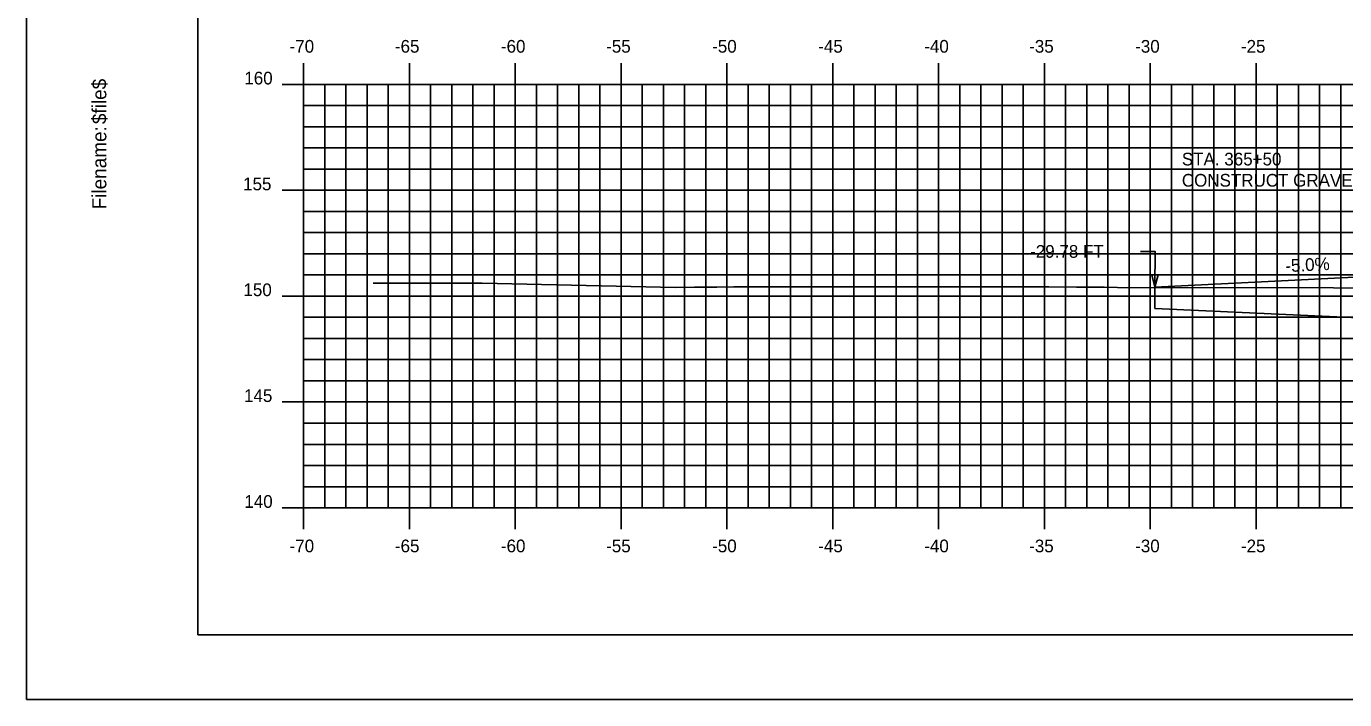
# Model space of a CAD drawing. Extents: x 1147412 to 1147582, y 608981 to 609091.
# Drawn here: x 1147411.6 to 1147473.9, y 608981.3 to 609013.1 of the extents above; entities that cross this region are included whole.
import ezdxf

# ---------------------------------------------------------------- set-up
doc = ezdxf.new("R2010")
doc.units = 0
for name, color, linetype in [('ANNOTATION', 7, 'Continuous'), ('BORDER', 7, 'Continuous'), ('D_Roadway_SubGrade', 7, 'Continuous'), ('D_Text_Standard', 7, 'Continuous'), ('H_V ANNOTATION', 7, 'Continuous'), ('MAJOR', 7, 'Continuous'), ('MINOR', 7, 'Continuous'), ('PLOT BOUNDARY', 7, 'Continuous'), ('S_Roadway_Centerline', 7, 'Continuous')]:
    doc.layers.add(name, color=color, linetype=linetype)

msp = doc.modelspace()

# ---------------------------------------------------------------- linework, layer by layer
msp.add_lwpolyline([(1147464.922, 609000.756), (1147479.697, 609001.495), (1147483.697, 609001.655), (1147494.697, 609001.875), (1147505.697, 609001.655), (1147509.697, 609001.495), (1147517.421, 608998.921), (1147520.421, 608997.921), (1147520.898, 608998.159), (1147522.148, 608998.709), (1147523.398, 608999.109), (1147524.648, 608999.359), (1147525.898, 608999.459)])
at = {"layer": 'BORDER'}
msp.add_lwpolyline([(1147419.698, 608984.335), (1147579.698, 608984.335), (1147579.698, 609089.335), (1147419.698, 609089.335)], close=True, dxfattribs=at)
at = {"layer": 'D_Roadway_SubGrade'}
msp.add_lwpolyline([(1147464.922, 608999.756), (1147479.697, 608999.075), (1147483.697, 608999.155), (1147483.697, 609001.239), (1147483.697, 609001.405), (1147479.697, 609001.245), (1147479.697, 609001.495), (1147464.922, 609000.756)], close=True, dxfattribs=at)
at = {"layer": 'D_Text_Standard'}
msp.add_lwpolyline([(1147464.922, 609000.756), (1147464.924, 609002.448), (1147464.244, 609002.448)], dxfattribs=at)
msp.add_lwpolyline([(1147464.922, 609000.756), (1147464.777, 609001.339), (1147465.068, 609001.338)], close=True, dxfattribs=at)
at = {"layer": 'MAJOR'}
for p, q in [((1147424.697, 609011.337), (1147424.697, 609010.335)), ((1147429.697, 609011.337), (1147429.697, 609010.335)), ((1147434.697, 609011.337), (1147434.697, 609010.335)), ((1147439.697, 609011.337), (1147439.697, 609010.335)), ((1147444.697, 609011.337), (1147444.697, 609010.335)), ((1147449.697, 609011.337), (1147449.697, 609010.335)), ((1147454.697, 609011.337), (1147454.697, 609010.335)), ((1147459.697, 609011.337), (1147459.697, 609010.335)), ((1147464.697, 609011.337), (1147464.697, 609010.335)), ((1147469.697, 609011.337), (1147469.697, 609010.335)), ((1147423.695, 609010.335), (1147424.697, 609010.335)), ((1147424.697, 609010.335), (1147564.697, 609010.335)), ((1147424.697, 608990.335), (1147424.697, 609010.335)), ((1147424.697, 608990.335), (1147424.697, 609010.335)), ((1147424.697, 609010.335), (1147564.697, 609010.335)), ((1147429.697, 608990.335), (1147429.697, 609010.335)), ((1147434.697, 608990.335), (1147434.697, 609010.335)), ((1147439.697, 608990.335), (1147439.697, 609010.335)), ((1147444.697, 608990.335), (1147444.697, 609010.335)), ((1147449.697, 608990.335), (1147449.697, 609010.335)), ((1147454.697, 608990.335), (1147454.697, 609010.335)), ((1147459.697, 608990.335), (1147459.697, 609010.335)), ((1147464.697, 608990.335), (1147464.697, 609010.335)), ((1147469.697, 608990.335), (1147469.697, 609010.335)), ((1147423.695, 609005.335), (1147424.697, 609005.335)), ((1147424.697, 609005.335), (1147564.697, 609005.335)), ((1147423.695, 609000.335), (1147424.697, 609000.335)), ((1147424.697, 609000.335), (1147564.697, 609000.335)), ((1147423.695, 608995.335), (1147424.697, 608995.335)), ((1147424.697, 608995.335), (1147564.697, 608995.335)), ((1147423.695, 608990.335), (1147424.697, 608990.335)), ((1147424.697, 608990.335), (1147564.697, 608990.335)), ((1147424.697, 608990.335), (1147564.697, 608990.335)), ((1147424.697, 608989.333), (1147424.697, 608990.335)), ((1147429.697, 608989.333), (1147429.697, 608990.335)), ((1147434.697, 608989.333), (1147434.697, 608990.335)), ((1147439.697, 608989.333), (1147439.697, 608990.335)), ((1147444.697, 608989.333), (1147444.697, 608990.335)), ((1147449.697, 608989.333), (1147449.697, 608990.335)), ((1147454.697, 608989.333), (1147454.697, 608990.335)), ((1147459.697, 608989.333), (1147459.697, 608990.335)), ((1147464.697, 608989.333), (1147464.697, 608990.335)), ((1147469.697, 608989.333), (1147469.697, 608990.335))]:
    msp.add_line(p, q, dxfattribs=at)
at = {"layer": 'MINOR'}
for p, q in [((1147425.697, 608990.335), (1147425.697, 609010.335)), ((1147426.697, 608990.335), (1147426.697, 609010.335)), ((1147427.697, 608990.335), (1147427.697, 609010.335)), ((1147428.697, 608990.335), (1147428.697, 609010.335)), ((1147430.697, 608990.335), (1147430.697, 609010.335)), ((1147431.697, 608990.335), (1147431.697, 609010.335)), ((1147432.697, 608990.335), (1147432.697, 609010.335)), ((1147433.697, 608990.335), (1147433.697, 609010.335)), ((1147435.697, 608990.335), (1147435.697, 609010.335)), ((1147436.697, 608990.335), (1147436.697, 609010.335)), ((1147437.697, 608990.335), (1147437.697, 609010.335)), ((1147438.697, 608990.335), (1147438.697, 609010.335)), ((1147440.697, 608990.335), (1147440.697, 609010.335)), ((1147441.697, 608990.335), (1147441.697, 609010.335)), ((1147442.697, 608990.335), (1147442.697, 609010.335)), ((1147443.697, 608990.335), (1147443.697, 609010.335)), ((1147445.697, 608990.335), (1147445.697, 609010.335)), ((1147446.697, 608990.335), (1147446.697, 609010.335)), ((1147447.697, 608990.335), (1147447.697, 609010.335)), ((1147448.697, 608990.335), (1147448.697, 609010.335)), ((1147450.697, 608990.335), (1147450.697, 609010.335)), ((1147451.697, 608990.335), (1147451.697, 609010.335)), ((1147452.697, 608990.335), (1147452.697, 609010.335)), ((1147453.697, 608990.335), (1147453.697, 609010.335)), ((1147455.697, 608990.335), (1147455.697, 609010.335)), ((1147456.697, 608990.335), (1147456.697, 609010.335)), ((1147457.697, 608990.335), (1147457.697, 609010.335)), ((1147458.697, 608990.335), (1147458.697, 609010.335)), ((1147460.697, 608990.335), (1147460.697, 609010.335)), ((1147461.697, 608990.335), (1147461.697, 609010.335)), ((1147462.697, 608990.335), (1147462.697, 609010.335)), ((1147463.697, 608990.335), (1147463.697, 609010.335)), ((1147465.697, 608990.335), (1147465.697, 609010.335)), ((1147466.697, 608990.335), (1147466.697, 609010.335)), ((1147467.697, 608990.335), (1147467.697, 609010.335)), ((1147468.697, 608990.335), (1147468.697, 609010.335)), ((1147470.697, 608990.335), (1147470.697, 609010.335)), ((1147471.697, 608990.335), (1147471.697, 609010.335)), ((1147472.697, 608990.335), (1147472.697, 609010.335)), ((1147473.697, 608990.335), (1147473.697, 609010.335)), ((1147424.697, 609009.335), (1147564.697, 609009.335)), ((1147424.697, 609009.335), (1147425.699, 609009.335)), ((1147424.697, 609008.335), (1147564.697, 609008.335)), ((1147424.697, 609008.335), (1147425.699, 609008.335)), ((1147424.697, 609007.335), (1147564.697, 609007.335)), ((1147424.697, 609007.335), (1147425.699, 609007.335)), ((1147424.697, 609006.335), (1147564.697, 609006.335)), ((1147424.697, 609006.335), (1147425.699, 609006.335)), ((1147424.697, 609004.335), (1147564.697, 609004.335)), ((1147424.697, 609004.335), (1147425.699, 609004.335)), ((1147424.697, 609003.335), (1147564.697, 609003.335)), ((1147424.697, 609003.335), (1147425.699, 609003.335)), ((1147424.697, 609002.335), (1147564.697, 609002.335)), ((1147424.697, 609002.335), (1147425.699, 609002.335)), ((1147424.697, 609001.335), (1147564.697, 609001.335)), ((1147424.697, 609001.335), (1147425.699, 609001.335)), ((1147424.697, 608999.335), (1147564.697, 608999.335)), ((1147424.697, 608999.335), (1147425.699, 608999.335)), ((1147424.697, 608998.335), (1147564.697, 608998.335)), ((1147424.697, 608998.335), (1147425.699, 608998.335)), ((1147424.697, 608997.335), (1147564.697, 608997.335)), ((1147424.697, 608997.335), (1147425.699, 608997.335)), ((1147424.697, 608996.335), (1147564.697, 608996.335)), ((1147424.697, 608996.335), (1147425.699, 608996.335)), ((1147424.697, 608994.335), (1147564.697, 608994.335)), ((1147424.697, 608994.335), (1147425.699, 608994.335)), ((1147424.697, 608993.335), (1147564.697, 608993.335)), ((1147424.697, 608993.335), (1147425.699, 608993.335)), ((1147424.697, 608992.335), (1147564.697, 608992.335)), ((1147424.697, 608992.335), (1147425.699, 608992.335)), ((1147424.697, 608991.335), (1147564.697, 608991.335)), ((1147424.697, 608991.335), (1147425.699, 608991.335))]:
    msp.add_line(p, q, dxfattribs=at)
at = {"layer": 'PLOT BOUNDARY'}
msp.add_lwpolyline([(1147411.604, 608981.276), (1147581.604, 608981.276), (1147581.604, 609091.276), (1147411.604, 609091.276)], close=True, dxfattribs=at)
at = {"layer": 'S_Roadway_Centerline'}
msp.add_lwpolyline([(1147427.993, 609000.948), (1147428.132, 609000.948), (1147428.234, 609000.948), (1147428.442, 609000.947), (1147428.577, 609000.947), (1147428.828, 609000.946), (1147429.152, 609000.946), (1147429.346, 609000.946), (1147429.814, 609000.945), (1147430.093, 609000.945), (1147430.574, 609000.945), (1147431.149, 609000.946), (1147431.583, 609000.946), (1147432.58, 609000.947), (1147433.145, 609000.947), (1147442.277, 609000.751), (1147443.168, 609000.757), (1147444.23, 609000.764), (1147445.034, 609000.767), (1147445.611, 609000.769), (1147446.86, 609000.772), (1147457.584, 609000.774), (1147459.081, 609000.774), (1147459.91, 609000.772), (1147461.212, 609000.766), (1147462.519, 609000.755), (1147463.151, 609000.749), (1147473.359, 609000.721), (1147474.62, 609000.704)], dxfattribs=at)

# ---------------------------------------------------------------- texts
at = {"layer": 'ANNOTATION'}
for s, p in [('STA. 365+50', (1147466.191, 609006.509)), ('CONSTRUCT GRAVEL ENTRANCE', (1147466.191, 609005.507))]:
    msp.add_text(s, height=0.6, dxfattribs=at).set_placement(p)
msp.add_text('-5.0%', height=0.6, rotation=2.86241, dxfattribs=at).set_placement((1147471.095, 609001.466))
at = {"layer": 'BORDER'}
for s, p in [('$file$', (1147415.383, 609008.461)), ('Filename:', (1147415.383, 609004.433))]:
    msp.add_text(s, height=0.6696, rotation=90, dxfattribs=at).set_placement(p)
at = {"layer": 'D_Text_Standard'}
msp.add_text('-29.78 FT', height=0.6, dxfattribs=at).set_placement((1147459.024, 609002.148))
at = {"layer": 'H_V ANNOTATION'}
for s, p in [('-70', (1147424.039, 609011.835)), ('-65', (1147429.015, 609011.835)), ('-60', (1147434.023, 609011.835)), ('-55', (1147438.994, 609011.835)), ('-50', (1147444.002, 609011.835)), ('-45', (1147449.015, 609011.835)), ('-40', (1147454.023, 609011.835)), ('-35', (1147458.978, 609011.835)), ('-30', (1147463.986, 609011.835)), ('-25', (1147468.983, 609011.835)), ('160', (1147421.902, 609010.335)), ('155', (1147421.843, 609005.335)), ('150', (1147421.859, 609000.335)), ('145', (1147421.886, 608995.335)), ('140', (1147421.902, 608990.335)), ('-70', (1147424.039, 608988.235)), ('-65', (1147429.015, 608988.235)), ('-60', (1147434.023, 608988.235)), ('-55', (1147438.994, 608988.235)), ('-50', (1147444.002, 608988.235)), ('-45', (1147449.015, 608988.235)), ('-40', (1147454.023, 608988.235)), ('-35', (1147458.978, 608988.235)), ('-30', (1147463.986, 608988.235)), ('-25', (1147468.983, 608988.235))]:
    msp.add_text(s, height=0.6, dxfattribs=at).set_placement(p)
at = {"layer": 'MAJOR'}
msp.add_text('-', height=0.006, dxfattribs=at).set_placement((1147424.693, 608990.335))

doc.saveas('drawing.dxf')
